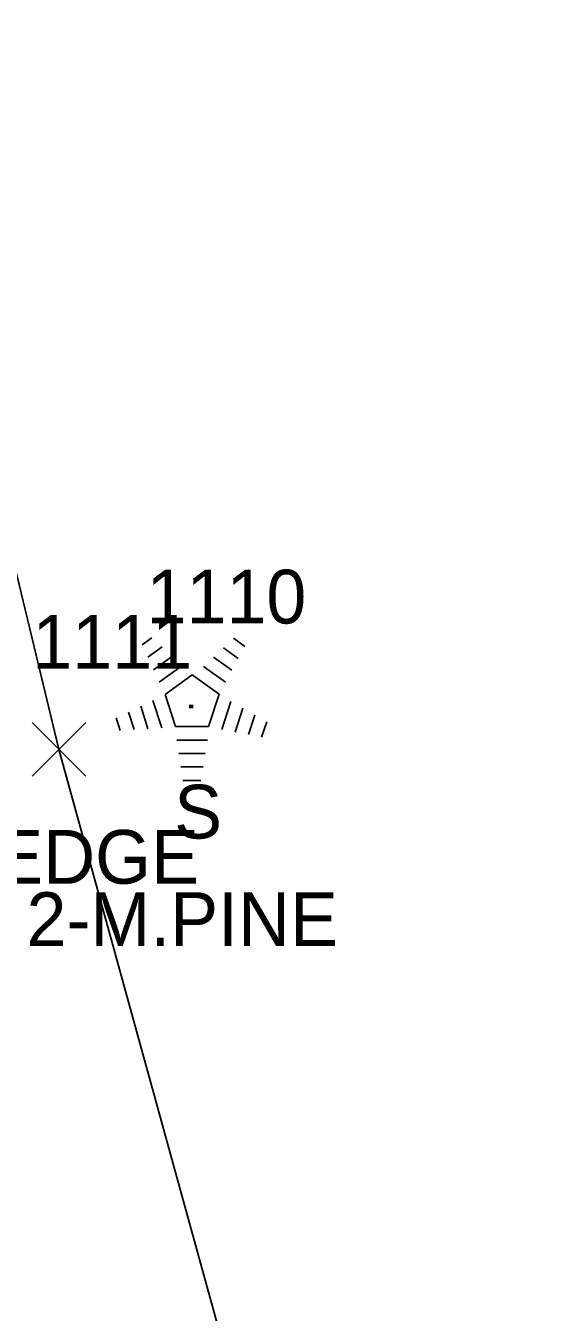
# Model space of a CAD drawing. Extents: x 1415642 to 1422021, y 544543 to 547232.
# Drawn here: x 1416560.65 to 1416579.62, y 546411.69 to 546459.56 of the extents above; entities that cross this region are included whole.
import ezdxf

# ---------------------------------------------------------------- set-up
doc = ezdxf.new("R2010")
doc.units = 0
for name, color, linetype in [('L_A', 7, 'Continuous'), ('L_C', 7, 'Continuous'), ('L_I', 7, 'Continuous'), ('L_TIC', 7, 'Continuous'), ('LAHR', 7, 'Continuous'), ('LTC', 7, 'Continuous')]:
    doc.layers.add(name, color=color, linetype=linetype)

msp = doc.modelspace()

# ---------------------------------------------------------------- linework, layer by layer
at = {"layer": 'L_TIC'}
for points in [[(1416560.883, 546431.633), (1416562.883, 546433.633)], [(1416562.883, 546431.633), (1416560.883, 546433.633)]]:
    msp.add_lwpolyline(points, dxfattribs=at)
at = {"layer": 'LAHR'}
for points in [[(1416579.616, 546377.828), (1416571.958, 546396.115), (1416561.883, 546432.634), (1416555.382, 546459.555)], [(1416579.616, 546377.827), (1416571.958, 546396.117), (1416561.883, 546432.633), (1416555.385, 546459.553)]]:
    msp.add_lwpolyline(points, dxfattribs=at)
at = {"layer": 'LTC'}
for p, q in [((1416564.984, 546436.523), (1416565.338, 546436.78)), ((1416565.193, 546436.057), (1416565.723, 546436.442)), ((1416568.382, 546436.763), (1416568.801, 546436.459)), ((1416565.403, 546435.592), (1416566.107, 546436.103)), ((1416567.64, 546436.067), (1416568.319, 546435.573)), ((1416568.011, 546436.415), (1416568.56, 546436.016)), ((1416565.613, 546435.126), (1416566.491, 546435.764)), ((1416567.269, 546435.718), (1416568.078, 546435.13)), ((1416565.837, 546434.671), (1416566.849, 546435.405)), ((1416566.849, 546435.405), (1416567.846, 546434.68)), ((1416565.837, 546434.671), (1416566.224, 546433.477)), ((1416567.846, 546434.68), (1416567.455, 546433.477)), ((1416564.927, 546434.235), (1416565.198, 546433.4)), ((1416565.383, 546434.452), (1416565.713, 546433.432)), ((1416568.283, 546434.41), (1416567.945, 546433.37)), ((1416568.728, 546434.159), (1416568.44, 546433.275)), ((1416564.016, 546433.802), (1416564.168, 546433.334)), ((1416564.472, 546434.019), (1416564.683, 546433.367)), ((1416569.173, 546433.909), (1416568.935, 546433.18)), ((1416569.617, 546433.659), (1416569.43, 546433.085)), ((1416567.455, 546433.477), (1416566.224, 546433.477)), ((1416567.416, 546432.977), (1416566.272, 546432.977)), ((1416567.333, 546432.477), (1416566.344, 546432.477)), ((1416567.249, 546431.977), (1416566.417, 546431.977)), ((1416567.165, 546431.477), (1416566.49, 546431.477))]:
    msp.add_line(p, q, dxfattribs=at)

# ---------------------------------------------------------------- texts
at = {"layer": 'L_A'}
for s, p in [('S', (1416566.174, 546429.315)), ('HEDGE', (1416557.584, 546427.633))]:
    msp.add_text(s, height=2, dxfattribs=at).set_placement(p)
at = {"layer": 'L_C'}
msp.add_text('2-M.PINE', height=2, dxfattribs=at).set_placement((1416560.678, 546425.315))
at = {"layer": 'L_I'}
for s, p in [('1110', (1416565.143, 546437.315)), ('1111', (1416560.891, 546435.633))]:
    msp.add_text(s, height=2, dxfattribs=at).set_placement(p)
at = {"layer": 'LTC'}
msp.add_text('.', height=1.037, rotation=270, dxfattribs=at).set_placement((1416566.731, 546434.419))

doc.saveas('drawing.dxf')
